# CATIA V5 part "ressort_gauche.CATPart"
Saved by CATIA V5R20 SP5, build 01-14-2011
Part number: ressort_gauche
Bounding box of the stored display mesh (mm): x 0 to 10, y -63.604 to 33.396, z -11.645 to 31.355
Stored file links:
  H:\EU_thinkMotion\IAO_2010\iao\IAO_MMS_Groupe3\PB\jpeguet\jpeguet_IAO\jpeguet_IAO\ressort_gauche.CATPart
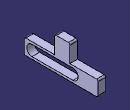
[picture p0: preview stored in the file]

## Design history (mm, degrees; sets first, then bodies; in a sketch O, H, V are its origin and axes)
Body1 (main body)
  Sketch1 on yz-plane, origin (0, 0, 0), H (0, 1, 0), V (0, 0, 1)
    line L1 (-23.6044, 31.3549) -> (-3.6044, 31.3549)
    line L2 (-3.6044, 31.3549) -> (-3.6044, -11.6451)
    line L3 (-3.6044, -11.6451) -> (-23.6044, -11.6451)
    line L4 (-23.6044, -11.6451) -> (-23.6044, 31.3549)
    length L1 = 20
    length L2 = 43
    horizontal: L1 H, L3 H
    vertical: L2 V, L4 V
  Pad1: profile Sketch1, direction (1, 0, 0), length 10
  Sketch2 on start face of Pad1, origin (0, 0, 0), H (0, -1, 0), V (0, 0, 1)
    arc A1 centre (13.6044, 21.3549) radius 7 from (14.6044, 14.4267) to (12.6044, 14.4267) ccw
    point P1 (13.6044, 21.3549)
    point P2 (12.6044, 12.5144)
    line L1 (14.6044, 14.4267) -> (14.6044, 17.3549)
    line L2 (14.6044, 17.3549) -> (12.6044, 17.3549)
    line L3 (12.6044, 17.3549) -> (12.6044, 14.4267)
    point P3 (14.6044, 12.5144)
    reference projected line E1 (23.6044, 31.3549) -> (23.6044, -28.6451) from edge [start face of Pad1 | face of Pad1 from Sketch1.L4]
    reference projected line E2 (3.6044, 31.3549) -> (23.6044, 31.3549) from edge [start face of Pad1 | face of Pad1 from Sketch1.L1]
    reference projected line E3 (23.6044, 31.3549) -> (23.6044, -28.6451) from edge [start face of Pad1 | face of Pad1 from Sketch1.L4]
    reference projected line E4 (3.6044, 31.3549) -> (23.6044, 31.3549) from edge [start face of Pad1 | face of Pad1 from Sketch1.L1]
    distance P1 E1 = 10
    distance E2 P1 = 10
    distance L1 E3 = 9
    radius A1 = 7
    distance L2 E4 = 14
    horizontal: L2 H
    vertical: L1 V, L3 V
  Pocket1: profile Sketch2, direction (1, 0, 0), length 3
  Sketch3 on face of Pad1 from Sketch1.L2, origin (0, -3.6044, 0), H (-1, 0, 0), V (0, 0, 1)
    line L1 (-10, -11.6451) -> (0, -11.6451)
    line L2 (0, -11.6451) -> (0, 8.3549)
    line L3 (0, 8.3549) -> (-10, 8.3549)
    line L4 (-10, 8.3549) -> (-10, -11.6451)
    reference projected line E1 (0, -11.6451) -> (-10, -11.6451) from edge [face of Pad1 from Sketch1.L2 | face of Pad1 from Sketch1.L3]
    reference projected line E2 (0, -8.6451) -> (0, 31.3549) from edge [start face of Pad1 | face of Pad1 from Sketch1.L2]
    reference projected line E3 (-10, -8.6451) -> (-10, 31.3549) from edge [face of Pad1 from Sketch1.L2 | end face of Pad1]
    length L2 = 20
    horizontal: L1 H, L3 H
    vertical: L2 V, L4 V
    coincidence: L1 E1, L2 E2, L4 E3
  Pad2: profile Sketch3, direction (0, 1, 0), length 37
  Sketch4 on face of Pad1 from Sketch1.L4, origin (0, -23.6044, 0), H (1, 0, 0), V (0, 0, 1)
    line L1 (10, -11.6451) -> (0, -11.6451)
    line L2 (0, -11.6451) -> (0, 8.3549)
    line L3 (0, 8.3549) -> (10, 8.3549)
    line L4 (10, 8.3549) -> (10, -11.6451)
    reference projected line E1 (0, -11.6451) -> (10, -11.6451) from edge [face of Pad2 | face of Pad1 from Sketch1.L4]
    reference projected line E2 (10, 31.3549) -> (10, -8.6451) from edge [face of Pad1 from Sketch1.L4 | face of Pad2]
    reference projected line E3 (0, 31.3549) -> (0, -8.6451) from edge [face of Pad2 | face of Pad1 from Sketch1.L4]
    length L4 = 20
    horizontal: L1 H, L3 H
    vertical: L2 V, L4 V
    coincidence: L1 E1, L4 E2, L2 E3
  Pad3: profile Sketch4, direction (0, -1, 0), length 40
  Sketch5 on face of Pad3, origin (10, 0, 0), H (0, 1, 0), V (0, 0, 1)
    construction line L1 (-53.6044, -1.6451) -> (0.3956, -1.6451)
    point P1 (-53.6044, -1.6451)
    point P2 (0.3956, -1.6451)
    line L2 (-53.6044, 5.3549) -> (0.3956, 5.3549)
    line L3 (0.3956, -8.6451) -> (-53.6044, -8.6451)
    arc A1 centre (0.3956, -1.6451) radius 7 from (0.3956, 5.3549) to (0.3956, -8.6451) cw
    arc A2 centre (-53.6044, -1.6451) radius 7 from (-53.6044, -8.6451) to (-53.6044, 5.3549) cw
    reference projected line E1 (-23.6044, -11.6451) -> (-3.6044, -11.6451) from edge [face of Pad3 | face of Pad3]
    reference projected line E2 (33.3956, 11.3549) -> (33.3956, -8.6451) from edge [face of Pad3 | end face of Pad2]
    reference projected line E3 (-63.6044, -8.6451) -> (-63.6044, 11.3549) from edge [face of Pad3 | end face of Pad3]
    distance L1 L2 = 7
    distance L1 E1 = 10
    distance P2 E2 = 33
    distance P1 E3 = 10
    horizontal: L1 H
    tangency: A1 L2, A2 L2, A1 L3, A2 L3
  Pocket2: profile Sketch5, direction (-1, 0, 0), through (limit type 3)
  Fillet1: radius 2, on edge [face of Pad1 from Sketch1.L1 | face of Pad1 from Sketch1.L2]; edge [face of Pad2 from Sketch3.L3 | end face of Pad2]; edge [face of Pad1 from Sketch1.L4 | face of Pad1 from Sketch1.L1]; edge [face of Pad3 from Sketch4.L3 | end face of Pad3]; edge [face of Pad3 | end face of Pad3]; edge [face of Pad3 | end face of Pad2]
